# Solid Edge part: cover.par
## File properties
Author: Robert a Rhodes jr
Template: NORMENG.PAR
Last saved by: CADCIM
Revision: 5
Application: Solid Edge
Density: 0 lbm/in^3
Accuracy: 0.99
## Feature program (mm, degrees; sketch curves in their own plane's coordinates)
sketch for "unnamed Protrusion 1" plane through (0, 0, 0) normal (0, 0, 1) x-axis (1, 0, 0)
  line (0, 0) -> (0, 0)
  circle centre (0, 0) radius 88.9
extrude "unnamed Protrusion 1" add finite 63.5 along -normal
fillet "Round_1" radius 25.4
thinwall "Thinwall_1"  Thickness = 6.35 mm
sketch for "ExtrudedProtrusion_3" #1 plane through (-1.5818, 0.3164, -63.5) normal (0, 0, -1) x-axis (-1, 0, 0)
  circle centre (-1.5818, 107.6336) radius 9.525
sketch for "ExtrudedProtrusion_3" #2 plane through (-1.5818, 0.3164, -63.5) normal (0, 0, -1) x-axis (-1, 0, 0)
  line (-20.6318, 86.5186) -> (-20.6318, 107.6336)
  arc centre (-1.5818, 107.6336) radius 19.05 from (-20.6318, 107.6336) to (17.4682, 107.6336) cw
  line (17.4682, 107.6336) -> (17.4682, 86.5186)
  arc centre (-1.5818, -0.3164) radius 88.9 from (17.4682, 86.5186) to (-20.6318, 86.5186) ccw
extrude "ExtrudedProtrusion_3" add finite 12.7 along -normal
pattern "unnamed Pattern 1" of "ExtrudedProtrusion_3"
extrude "unnamed Protrusion 2" add finite 12.7
extrude "unnamed Protrusion 3" add finite 12.7
sketch for "ExtrudedProtrusion_6" plane through (0, 0, 0) normal (0, 0, 1) x-axis (1, 0, 0)
  circle centre (0, 0) radius 31.75
extrude "ExtrudedProtrusion_6" add finite 19.05 along +normal
fillet "Round_2" radius 5.08
sketch used by "unnamed Cutout 1" plane through (0, 0, 0) normal (0, 0, 1) x-axis (1, 0, 0)
extrude "unnamed Cutout 1" cut through along -normal
pattern "unnamed Pattern 2" of "unnamed Cutout 1"
extrude "unnamed Cutout 2" cut through
extrude "unnamed Cutout 3" cut through
extrude "unnamed Cutout 4" cut through
extrude "unnamed Cutout 5" cut through
extrude "unnamed Cutout 6" cut through
extrude "unnamed Cutout 7" cut through
sketch for "unnamed Protrusion 4" plane through (0, 0, 0) normal (0, 0, -1) x-axis (0, -1, 0)
  circle centre (0, 0) radius 31.75
extrude "unnamed Protrusion 4" add along +normal
sketch for "Hole_1" plane through (0, 0, 19.05) normal (0, 0, 1) x-axis (1, 0, 0)
  hole centre (0, 0) bore radius 19.05
hole "Hole_1" diameter 38.1 through
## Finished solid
Body 1: solid body, 66 faces, 205 edges, 128 vertices.
  Faces by surface: plane 39, cylinder 24, torus 3
  Edges by curve: line 112, circle 69, intersection 24
Bounding box of the edges (mm; curved faces can reach further): 225.075 x 215.900 x 82.550, from (-112.5374, -88.9, -63.5) to (112.5374, 127, 19.05).
Cylindrical faces by radius (mm): R3.81 x14, R9.525 x3, R19.05 x4, R31.75 x1, R82.55 x1, R88.9 x1
Toroidal faces (ring radius, tube radius in mm): R26.67 r5.08 x1, R63.5 r19.05 x1, R63.5 r25.4 x1
Planar faces by outward normal: +x 12, +z 7, -x 12, -z 4, oblique 4
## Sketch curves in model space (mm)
arc centre (-45.72, -50.8, 0) radius 3.81 from (-41.91, -50.8, 0) through (-45.8329, -54.6083, 0) to (-49.53, -50.8, 0)
line (-49.53, -50.8, 0) -> (-49.53, 50.8, 0)
arc centre (-45.72, 50.8, 0) radius 3.81 from (-49.53, 50.8, 0) through (-45.6071, 54.6083, 0) to (-41.91, 50.8, 0)
line (-41.91, 50.8, 0) -> (-41.91, -50.8, 0)
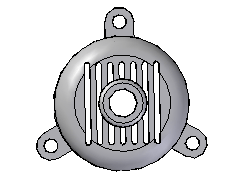
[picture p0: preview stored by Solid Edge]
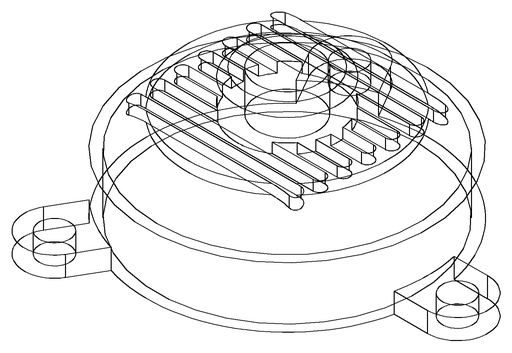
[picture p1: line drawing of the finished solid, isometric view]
